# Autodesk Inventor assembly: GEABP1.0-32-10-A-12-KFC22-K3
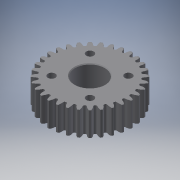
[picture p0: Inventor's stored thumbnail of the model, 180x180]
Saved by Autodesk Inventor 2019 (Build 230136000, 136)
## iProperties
Category: PARTsolutions
Company: MISUMI
Created: 2022-11
Part Number: GEABP1.0-32-10-A-12-KFC22-K3
Catalog Web Link: www.cadenas.de
Description: GEABM, GEABMS, GEABMT, GEABP, GEABPS, GEABPT, GEABA, GEABAS, GEABAT-Plastic Spur Gears - Pressure Angle 20 Degrees, Module 0.5/0.8/1.0/1.5/2.0/2.5/3.0
Vendor: MISUMI
Document SubType Name: Assembly
Designer: psAdmin
Manufacturer: MISUMI
Mass: 6.51664 g
Surface Area: 40.015 cm^2
Volume: 6.51664 cm^3
Density: 1 g/cm^3
Title: GEABP1.0-32-10-A-12-KFC22-K3
Author: Cadenas PARTsolutions
Comments: Plastic Spur Gears - Pressure Angle 20 Degrees, Module 0.5/0.8/1.0/1.5/2.0/2.5/3.0
PSOL_IDENT_0: {$CADENAS_DATA/23d-libs/misumi/metric/54_spur_gears/geabms20_asmtab.prj},415 {VTYP=3D},{STYP=ASSTAB}
PSOL_IDENT_1: ,{NB=GEABP1.0-32-10-A-12-KFC22-K3},{LINA=GEABP1.0-32-10-A-12-KFC22-K3},{NN=GEABM, GEABMS, GEABMT, GE
PSOL_IDENT_2: ABP, GEABPS, GEABPT, GEABA, GEABAS, GEABAT},{DATE=16.08.2021 10:08:31},{GEOMDATE=16.08.2021 10:08:28
PSOL_IDENT_3: },{VERSION=},{LINEID=30},{WBVAR=MATSG,MATCR,NT,B,TS,PS,ALT1,ALT2,TPC,ALT11,ALT10,BS,ALT3,Z,J,ALT4,Q,
PSOL_IDENT_4: R,S,T,ALT5,LFC,LTC,MALT5,ALT6,KFC,KTC,K},{WBNUMERIC=NT,B,BS,Z,J,Q,R,S,T,LFC,LTC,KFC,KTC,K}  {NB=GEAB
PSOL_IDENT_5: P1.0-32-10-A-12-KFC22-K3},{LINA=GEABP1.0-32-10-A-12-KFC22-K3},{KT=DUMMY},{PN=GEABP1.0-32-10-A-12-KFC
PSOL_IDENT_6: 22-K3},{TYPE=GEABP},{MATSG=PW},{MATSGALG='MCN','MC Nylon','PW','Polyacetal White','PB','Polyacetal B
PSOL_IDENT_7: lue'},{MATCR=},{MATCRALG='','-','S45C','1045 Carbon Steel','SUS304','304 Stainless Steel'},{MOD=1.0}
PSOL_IDENT_8: ,{MOD1=1.0},{NT=32},{NTALG=15,16,18,20,22,24,25,26,28,30,32,35,36,40,45,48,50,55,60,70,75,80,90,100,
PSOL_IDENT_9: 120},{B=10},{BALG=10,15},{TS=A},{TSALG='A','A','B','B'},{TSPN=-A},{PS=12},{PSALG='10','10','11','11'
PSOL_IDENT_10: ,'12','12','13','13','14','14','15','15','16','16','17','17','18','18'},{PSCRL='10','10','11','11','
PSOL_IDENT_11: 12','12','13','13','14','14','15','15','16','16','17','17','18','18'},{PSCRW='10','10','12','12'},{D
PSOL_IDENT_12: D=32.0},{DD05=16},{DD08=25.6},{DD10=32},{DD15=48},{DD20=64},{DD25=80},{DD30=96},{D=34.0},{D05=17},{D
PSOL_IDENT_13: 08=27.2},{D10=34},{D15=51},{D20=68},{D25=85},{D30=102},{G=29.50},{G05=14.75},{G08=23.6},{G10=29.5},{
PSOL_IDENT_14: G15=44.25},{G20=59},{G25=73.75},{G30=88.5},{H=0.0},{L=0},{LL1=0},{LL2=0.0},{M=-},{M3D=0},{P=12.00},{
PSOL_IDENT_15: DD1=0},{CIFR=15},{CIFM=0},{CIFK=0},{CIFTAP=0},{SCREW=0.000},{SCREWL=0.000},{ALT1=},{ALT1ALG='','Not
PSOL_IDENT_16: applicable'},{ALT1PN=},{ALT2=},{ALT2ALG='','Not applicable'},{TPC=N/A},{TPCALG='N/A'},{ALT2PN=},{KC=
PSOL_IDENT_17: 0},{ALT11=},{ALT11ALG='','Not applicable'},{ALT11PN=},{DEG=0},{ALT10=},{ALT10ALG= '','Not applicable'
PSOL_IDENT_18: },{ALT10PN=},{BS=0.0},{BSALG=0},{BSMIN=3.000},{BSMINALG=3},{BSMAX=0},{LL13D=0},{LL23D=0},{ALT3=},{A
PSOL_IDENT_19: LT3ALG= '','w/o Stepped Hole','DHL','with DHL (Stepped Hole)','DHR','with DHR (Stepped Hole)' },{ALT
PSOL_IDENT_20: 3PN=},{ZJPN=},{ALT31=1},{ALT32=1},{Z=0},{ZALG=0},{ZMINL=14},{ZMAXL=25},{ZMINR=14},{ZMAXR=25},{ZPN=},
PSOL_IDENT_21: {J=0.0},{JALG=0},{JMIN=2},{JMAX=0},{JPN=},{ALT4=},{ALT4ALG= '','w/o WDH (Both Ends Stepped Hole)','W
PSOL_IDENT_22: DH','with WDH (Both Ends Stepped Hole)' },{ALT4PN=},{QRSTPN=},{LB=10.000},{Q=0},{QALG=0},{QMIN=14},{
PSOL_IDENT_23: QMAX=25},{QPN=},{R=0},{RALG=0},{RMIN=14},{RMAX=25},{RPN=},{S=0},{SALG=0},{SMIN=3},{SMAX=4},{SPN=},{T=
PSOL_IDENT_24: 0},{TALG=0},{TMIN=3},{TMAX=0},{TPN=},{ALT5=},{ALT5ALG= '','w/o Side Slotted Hole','LFC','with LFC (S
PSOL_IDENT_25: ide Slotted Hole)','LTC','with LTC (Side Slotted Hole)' },{LFC=0},{LFCALG=0},{LTC=0},{LTCALG=0},{LPC
PSOL_IDENT_26: DMIN=20},{LPCDMAX=22},{LCMAX=25},{MALT5=N/A},{MALT5ALG= 'N/A' },{LCMAX2=22},{C=0.0},{ALT5PN=},{ALT6=
PSOL_IDENT_27: KFC},{ALT6ALG= '','w/o Side Through Hole','KFC','with KFC (Side Through Hole)','KTC','with KTC (Side
PSOL_IDENT_28: Through Hole)' },{ALT6PN=-KFC},{KFTCPN=22-K3},{KFC=22},{KFCALG=[19:22/1]},{KFCPN=22},{KTC=0},{KTCAL
PSOL_IDENT_29: G=[0]},{KTCPN=},{KPCDMIN1=19},{KPCDMAX1=-7},{KPCDMIN2=7},{KPCDMAX2=22},{K=3.0},{KALG=[3:3.5/0.5]},{K
PSOL_IDENT_30: PCD=22},{KPN=-K3},{AG=0},{LBS=10},{PCD=22},{SHN=4},{SHDEG1=45},{SHDEG2=90},{PZQRDD2=12},{PPATH=geabm
PSOL_IDENT_31: s20/geabms20_asmtpl.prj}
NB: GEABP1.0-32-10-A-12-KFC22-K3
NN: GEABM, GEABMS, GEABMT, GEABP, GEABPS, GEABPT, GEABA, GEABAS, GEABAT
NT: 32
NBSYN: $PN.
LINA: GEABP1.0-32-10-A-12-KFC22-K3
CATALOG: Misumi
PN: GEABP1.0-32-10-A-12-KFC22-K3
MATSG: Polyacetal White
MATCR: -
MOD: 1.0
B: 10
TS: A
PS: 12
DD: 32
D: 34
G: 29.5
H: 0
L: 0
LL1: 0
LL2: 0
M: -
DD1: 0
ALT1: Not applicable
ALT2: Not applicable
TPC: N/A
ALT11: Not applicable
ALT10: Not applicable
BS: 0
ALT3: w/o Stepped Hole
Z: 0
J: 0
ALT4: w/o WDH (Both Ends Stepped Hole)
Q: 0
R: 0
S: 0
T: 0
ALT5: w/o Side Slotted Hole
LFC: 0
LTC: 0
MALT5: N/A
C: 0
ALT6: with KFC (Side Through Hole)
KFC: 22
KTC: 0
K: 3
SUPPLIER: MISUMI
ARTICLENO: GEABP1.0-32-10-A-12-KFC22-K3
BOMINFO: GEABP1.0-32-10-A-12-KFC22-K3
CREATOR: CADENAS GmbH
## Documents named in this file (2)
- e:\temp\worker_COMMON_12\temp\tmp_8848_148_Gzg7B\format_0\GEABP1_0-32-10-A-12-KFC22-K3.iam
- e:\temp\worker_COMMON_12\temp\tmp_8848_148_Gzg7B\format_0\GEABP1_0-32-10-A-12-KFC22-K3_b.ipt
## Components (1 placed, 1 different names)
1. GEABP1_0-32-10-A-12-KFC22-K3_b:1
